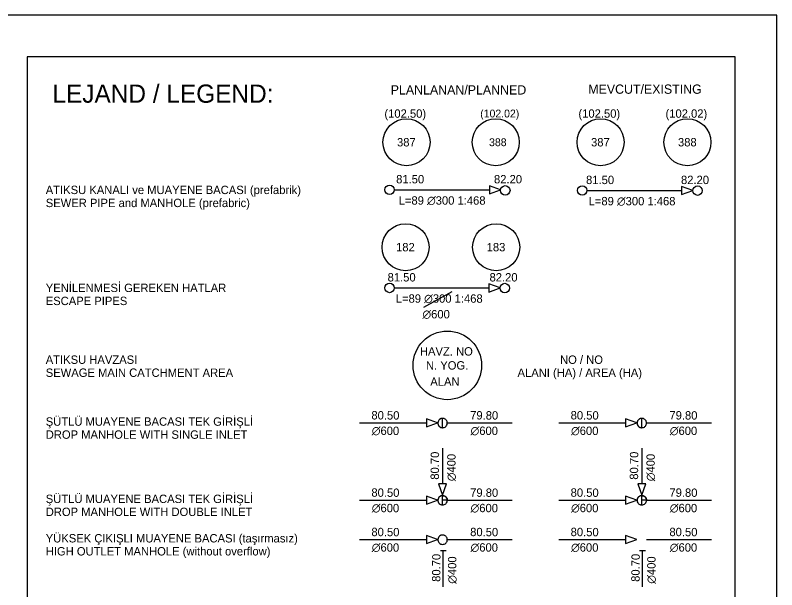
# Model space of a CAD drawing. Extents: x -10 to 1145, y -10 to 821.
# Drawn here: x 962.1 to 1145, y 683 to 821 of the extents above; entities that cross this region are included whole.
import ezdxf

# ---------------------------------------------------------------- set-up
doc = ezdxf.new("R2010")
doc.units = 0
for name, color, linetype in [('Level 1', 7, 'Continuous'), ('Level 10', 7, 'Continuous'), ('Level 11', 7, 'Continuous'), ('Level 12', 7, 'Continuous'), ('Level 13', 7, 'Continuous'), ('Level 15', 7, 'Continuous'), ('Level 16', 7, 'Continuous'), ('Level 17', 7, 'Continuous'), ('Level 31', 7, 'Continuous'), ('Level 32', 7, 'Continuous'), ('Level 39', 7, 'Continuous'), ('Level 51', 7, 'Continuous'), ('Level 52', 7, 'Continuous')]:
    doc.layers.add(name, color=color, linetype=linetype)

msp = doc.modelspace()

# ---------------------------------------------------------------- linework, layer by layer
at = {"layer": 'Level 10'}
for points in [[(1063.61, 723.04), (1063.61, 722.9), (1063.65, 722.68), (1063.73, 722.52), (1063.84, 722.34), (1063.98, 722.17), (1064.11, 722.08), (1064.3, 721.98), (1064.49, 721.92), (1064.74, 721.89), (1064.97, 721.92), (1065.16, 721.97), (1065.36, 722.06), (1065.5, 722.15), (1065.64, 722.3), (1065.71, 722.42), (1065.82, 722.63), (1065.86, 722.82), (1065.88, 722.99), (1065.86, 723.19), (1065.82, 723.38), (1065.76, 723.52), (1065.63, 723.74), (1065.5, 723.86), (1065.33, 723.97), (1065.23, 724.04), (1065.11, 724.09), (1064.92, 724.12), (1064.75, 724.15), (1064.57, 724.12), (1064.36, 724.09), (1064.21, 724.01), (1063.99, 723.86), (1063.86, 723.7), (1063.73, 723.51), (1063.65, 723.27), (1063.61, 723.01)], [(1111.46, 723.04), (1111.46, 722.9), (1111.5, 722.68), (1111.57, 722.52), (1111.68, 722.34), (1111.83, 722.17), (1111.96, 722.08), (1112.14, 721.98), (1112.34, 721.92), (1112.59, 721.89), (1112.82, 721.92), (1113.01, 721.97), (1113.21, 722.06), (1113.35, 722.15), (1113.48, 722.3), (1113.56, 722.42), (1113.67, 722.63), (1113.7, 722.82), (1113.72, 722.99), (1113.7, 723.19), (1113.67, 723.38), (1113.6, 723.52), (1113.47, 723.74), (1113.35, 723.86), (1113.18, 723.97), (1113.08, 724.04), (1112.96, 724.09), (1112.76, 724.12), (1112.6, 724.15), (1112.41, 724.12), (1112.21, 724.09), (1112.06, 724.01), (1111.84, 723.86), (1111.7, 723.7), (1111.57, 723.51), (1111.5, 723.27), (1111.46, 723.01)], [(1063.61, 704.48), (1063.61, 704.34), (1063.65, 704.12), (1063.73, 703.96), (1063.84, 703.78), (1063.98, 703.61), (1064.11, 703.52), (1064.3, 703.42), (1064.49, 703.35), (1064.74, 703.33), (1064.97, 703.35), (1065.16, 703.41), (1065.36, 703.49), (1065.5, 703.59), (1065.64, 703.74), (1065.71, 703.86), (1065.82, 704.06), (1065.86, 704.26), (1065.88, 704.42), (1065.86, 704.63), (1065.82, 704.82), (1065.76, 704.96), (1065.63, 705.18), (1065.5, 705.3), (1065.33, 705.41), (1065.23, 705.48), (1065.11, 705.52), (1064.92, 705.56), (1064.75, 705.59), (1064.57, 705.56), (1064.36, 705.52), (1064.21, 705.45), (1063.99, 705.3), (1063.86, 705.13), (1063.73, 704.95), (1063.65, 704.71), (1063.61, 704.45)], [(1111.46, 704.48), (1111.46, 704.34), (1111.5, 704.12), (1111.57, 703.96), (1111.68, 703.78), (1111.83, 703.61), (1111.96, 703.52), (1112.14, 703.42), (1112.34, 703.35), (1112.59, 703.33), (1112.82, 703.35), (1113.01, 703.41), (1113.21, 703.49), (1113.35, 703.59), (1113.48, 703.74), (1113.56, 703.86), (1113.67, 704.06), (1113.7, 704.26), (1113.72, 704.42), (1113.7, 704.63), (1113.67, 704.82), (1113.6, 704.96), (1113.47, 705.18), (1113.35, 705.3), (1113.18, 705.41), (1113.08, 705.48), (1112.96, 705.52), (1112.76, 705.56), (1112.6, 705.59), (1112.41, 705.56), (1112.21, 705.52), (1112.06, 705.45), (1111.84, 705.3), (1111.7, 705.13), (1111.57, 704.95), (1111.5, 704.71), (1111.46, 704.45)], [(1063.61, 695.01), (1063.61, 694.87), (1063.65, 694.65), (1063.73, 694.49), (1063.84, 694.31), (1063.98, 694.14), (1064.11, 694.05), (1064.3, 693.95), (1064.49, 693.88), (1064.74, 693.86), (1064.97, 693.88), (1065.16, 693.94), (1065.36, 694.02), (1065.5, 694.12), (1065.64, 694.27), (1065.71, 694.39), (1065.82, 694.59), (1065.86, 694.79), (1065.88, 694.95), (1065.86, 695.16), (1065.82, 695.35), (1065.76, 695.49), (1065.63, 695.71), (1065.5, 695.83), (1065.33, 695.94), (1065.23, 696), (1065.11, 696.05), (1064.92, 696.09), (1064.75, 696.12), (1064.57, 696.09), (1064.36, 696.05), (1064.21, 695.98), (1063.99, 695.83), (1063.86, 695.66), (1063.73, 695.48), (1063.65, 695.24), (1063.61, 694.98)]]:
    msp.add_lwpolyline(points, dxfattribs=at)
for points in [[(1064.76, 721.89), (1064.75, 724.15), (1064.49, 724.1), (1064.39, 724.09), (1064.27, 724.04), (1064.17, 723.97), (1064, 723.86), (1063.87, 723.74), (1063.74, 723.52), (1063.68, 723.38), (1063.65, 723.24), (1063.64, 723.19), (1063.63, 723.09), (1063.62, 722.99), (1063.64, 722.82), (1063.68, 722.63), (1063.79, 722.42), (1063.86, 722.3), (1063.97, 722.19), (1064, 722.15), (1064.14, 722.06), (1064.28, 721.99), (1064.33, 721.97), (1064.48, 721.93), (1064.53, 721.92), (1064.64, 721.9)], [(1112.61, 721.89), (1112.6, 724.15), (1112.33, 724.1), (1112.24, 724.09), (1112.12, 724.04), (1112.01, 723.97), (1111.85, 723.86), (1111.72, 723.74), (1111.59, 723.52), (1111.53, 723.38), (1111.5, 723.24), (1111.49, 723.19), (1111.48, 723.09), (1111.47, 722.99), (1111.49, 722.82), (1111.53, 722.63), (1111.64, 722.42), (1111.71, 722.3), (1111.81, 722.19), (1111.85, 722.15), (1111.99, 722.06), (1112.13, 721.99), (1112.18, 721.97), (1112.33, 721.93), (1112.37, 721.92), (1112.49, 721.9)], [(1064.74, 703.33), (1064.75, 705.59), (1064.57, 705.56), (1064.46, 705.54), (1064.36, 705.52), (1064.25, 705.48), (1064.15, 705.41), (1063.98, 705.3), (1063.86, 705.18), (1063.73, 704.96), (1063.66, 704.82), (1063.63, 704.68), (1063.63, 704.63), (1063.62, 704.53), (1063.61, 704.42), (1063.63, 704.26), (1063.66, 704.06), (1063.77, 703.86), (1063.85, 703.74), (1063.95, 703.63), (1063.98, 703.59), (1064.12, 703.49), (1064.27, 703.43), (1064.32, 703.41), (1064.46, 703.37), (1064.51, 703.35), (1064.63, 703.34)], [(1064.74, 704.46), (1064.75, 705.59), (1064.86, 705.57), (1064.97, 705.56), (1065.07, 705.53), (1065.16, 705.51), (1065.26, 705.46), (1065.36, 705.42), (1065.43, 705.37), (1065.5, 705.32), (1065.57, 705.25), (1065.64, 705.17), (1065.67, 705.11), (1065.71, 705.05), (1065.77, 704.95), (1065.82, 704.85), (1065.85, 704.71), (1065.86, 704.62), (1065.87, 704.53), (1065.88, 704.49), (1065.87, 704.49)], [(1112.59, 703.33), (1112.6, 705.59), (1112.41, 705.56), (1112.31, 705.54), (1112.21, 705.52), (1112.1, 705.48), (1112, 705.41), (1111.83, 705.3), (1111.7, 705.18), (1111.57, 704.96), (1111.51, 704.82), (1111.48, 704.68), (1111.47, 704.63), (1111.46, 704.53), (1111.45, 704.42), (1111.47, 704.26), (1111.51, 704.06), (1111.62, 703.86), (1111.69, 703.74), (1111.8, 703.63), (1111.83, 703.59), (1111.97, 703.49), (1112.11, 703.43), (1112.16, 703.41), (1112.31, 703.37), (1112.36, 703.35), (1112.47, 703.34)], [(1112.58, 704.46), (1112.6, 705.59), (1112.7, 705.57), (1112.82, 705.56), (1112.92, 705.53), (1113.01, 705.51), (1113.11, 705.46), (1113.21, 705.42), (1113.28, 705.37), (1113.35, 705.32), (1113.41, 705.25), (1113.48, 705.17), (1113.52, 705.11), (1113.56, 705.05), (1113.61, 704.95), (1113.67, 704.85), (1113.7, 704.71), (1113.71, 704.62), (1113.72, 704.53), (1113.72, 704.49), (1113.72, 704.49)]]:
    msp.add_lwpolyline(points, close=True, dxfattribs=at)
for centre in [(1052, 779.06), (1079.81, 778.92), (1098.29, 778.89), (1125.98, 778.85), (1052, 755.47), (1079.68, 755.46)]:
    msp.add_circle(centre, 1.13, dxfattribs=at)
at = {"layer": 'Level 11'}
for centre in [(1056.08, 790.49), (1077.51, 790.49), (1102.68, 790.49), (1123.55, 790.49), (1055.85, 765.27), (1077.61, 765.27)]:
    msp.add_circle(centre, 5.65, dxfattribs=at)
at = {"layer": 'Level 15'}
for p, q in [((1053.13, 779.03), (1075.98, 779.03)), ((1099.43, 778.87), (1122.15, 778.87)), ((1053.13, 755.47), (1075.85, 755.47)), ((1044.82, 723.05), (1060.86, 723.05)), ((1065.73, 723.05), (1081.47, 723.05)), ((1092.67, 723.05), (1108.7, 723.05)), ((1113.57, 723.05), (1129.32, 723.05)), ((1064.74, 717.01), (1064.74, 708.39)), ((1112.58, 717.01), (1112.58, 708.39)), ((1044.82, 704.49), (1060.86, 704.49)), ((1065.87, 704.49), (1081.47, 704.49)), ((1092.67, 704.49), (1108.7, 704.49)), ((1113.72, 704.49), (1129.32, 704.49)), ((1044.82, 695.02), (1060.86, 695.02)), ((1065.87, 695.02), (1081.47, 695.02)), ((1092.67, 695.02), (1108.7, 695.02)), ((1113.72, 695.02), (1129.32, 695.02)), ((1064.22, 692.36), (1065.63, 692.36)), ((1064.92, 683.69), (1064.92, 692.36)), ((1112.06, 692.36), (1113.48, 692.36)), ((1112.77, 683.69), (1112.77, 692.36))]:
    msp.add_line(p, q, dxfattribs=at)
at = {"layer": 'Level 16'}
for points in [[(1078.68, 779.03), (1075.98, 780), (1075.98, 778.07)], [(1124.85, 778.87), (1122.15, 779.84), (1122.15, 777.9)], [(1078.56, 755.47), (1075.85, 756.43), (1075.85, 754.5)], [(1063.56, 723.05), (1060.86, 724.02), (1060.86, 722.08)], [(1111.41, 723.05), (1108.7, 724.02), (1108.7, 722.08)], [(1064.74, 705.68), (1065.7, 708.39), (1063.77, 708.39)], [(1112.58, 705.68), (1113.55, 708.39), (1111.62, 708.39)], [(1063.56, 704.49), (1060.86, 705.45), (1060.86, 703.52)], [(1111.41, 704.49), (1108.7, 705.45), (1108.7, 703.52)], [(1063.56, 695.02), (1060.86, 695.98), (1060.86, 694.05)], [(1111.41, 695.02), (1108.7, 695.98), (1108.7, 694.05)]]:
    msp.add_lwpolyline(points, close=True, dxfattribs=at)
at = {"layer": 'Level 17'}
msp.add_line((1060.22, 750.87), (1067.07, 754.59), dxfattribs=at)
at = {"layer": 'Level 31'}
msp.add_circle((1065.88, 736.87), 8.24, dxfattribs=at)
at = {"layer": 'Level 51'}
msp.add_lwpolyline([(-10, -10), (1145, -10), (1145, 821), (-10, 821)], close=True, dxfattribs=at)
at = {"layer": 'Level 52'}
msp.add_lwpolyline([(965, 287), (1135, 287), (1135, 811), (965, 811)], close=True, dxfattribs=at)

# ---------------------------------------------------------------- texts
at = {"layer": 'Level 1'}
for s, height, p in [('LEJAND / LEGEND:', 4.3826, (971.05, 799.97)), ('PLANLANAN/PLANNED', 2.2228, (1052.29, 801.95)), ('MEVCUT/EXISTING', 2.2228, (1099.73, 802.13)), ('ATIKSU KANALI ve MUAYENE BACASI (prefabrik)', 2.0119, (969.44, 778.03)), ('SEWER PIPE and MANHOLE (prefabric)', 2.0119, (969.44, 774.9)), ('YENİLENMESİ GEREKEN HATLAR', 2.0119, (969.44, 754.49)), ('ESCAPE PIPES', 2.0119, (969.44, 751.36)), ('ATIKSU HAVZASI', 2.0119, (969.44, 737.24)), ('SEWAGE MAIN CATCHMENT AREA', 2.0119, (969.44, 734.11)), ('ŞÜTLÜ MUAYENE BACASI TEK GİRİŞLİ', 2.0119, (969.44, 722.37)), ('DROP MANHOLE WITH SINGLE INLET', 2.0119, (969.44, 719.24)), ('ŞÜTLÜ MUAYENE BACASI TEK GİRİŞLİ', 2.0119, (969.44, 703.8)), ('DROP MANHOLE WITH DOUBLE INLET', 2.0119, (969.44, 700.68)), ('YÜKSEK ÇIKIŞLI MUAYENE BACASI (taşırmasız)', 2.0119, (969.44, 694.33)), ('HIGH OUTLET MANHOLE (without overflow)', 2.0119, (969.44, 691.2))]:
    msp.add_text(s, height=height, rotation=360, dxfattribs=at).set_placement(p)
at = {"layer": 'Level 12'}
for s, height, p in [('387', 2.012, (1053.8, 789.48)), ('388', 1.883, (1075.91, 789.54)), ('387', 2.012, (1100.4, 789.48)), ('388', 2.012, (1121.27, 789.48)), ('182', 2.012, (1053.57, 764.27)), ('183', 2.012, (1075.33, 764.27))]:
    msp.add_text(s, height=height, rotation=360, dxfattribs=at).set_placement(p)
at = {"layer": 'Level 13'}
for s, height, p in [('(102.50)', 2.012, (1050.77, 796.37)), ('(102.02)', 1.883, (1073.78, 796.44)), ('(102.50)', 2.012, (1097.37, 796.37)), ('(102.02)', 2.012, (1118.28, 796.37))]:
    msp.add_text(s, height=height, rotation=360, dxfattribs=at).set_placement(p)
at = {"layer": 'Level 17'}
for s, height, rotation, p in [('81.50', 2.012, 360, (1053.59, 780.6)), ('82.20', 2.012, 360, (1077.09, 780.6)), ('81.50', 2.012, 360, (1099.2, 780.43)), ('82.20', 2.012, 360, (1122, 780.43)), ('L=89 ∅300 1:468', 2.0119, 359.987, (1054.2, 775.49)), ('L=89 ∅300 1:468', 2.0119, 359.987, (1099.81, 775.33)), ('81.50', 2.012, 360, (1051.54, 757.03)), ('82.20', 2.012, 360, (1076.02, 757.03)), ('L=89 ∅300 1:468', 2.0119, 359.987, (1053.51, 751.93)), (' ∅600 ', 2.012, 359.987, (1059.16, 748.16)), ('80.50', 2.012, 359.5872, (1047.64, 723.89)), ('79.80', 2.012, 359.5872, (1071.36, 723.89)), ('80.50', 2.012, 359.5872, (1095.49, 723.89)), ('79.80', 2.012, 359.5872, (1119.21, 723.89)), ('∅600', 2.012, 359.5872, (1047.74, 720.18)), ('∅600', 2.012, 359.5872, (1071.46, 720.18)), ('∅600', 2.012, 359.5872, (1095.59, 720.18)), ('∅600', 2.012, 359.5872, (1119.31, 720.18)), ('80.70', 2.012, 89.5872, (1063.86, 709.4)), ('∅400', 2.012, 89.5872, (1067.83, 709.04)), ('80.70', 2.012, 89.5872, (1111.7, 709.4)), ('∅400', 2.012, 89.5872, (1115.67, 709.04)), ('80.50', 2.012, 359.5872, (1047.64, 705.32)), ('79.80', 2.012, 359.5872, (1071.36, 705.32)), ('80.50', 2.012, 359.5872, (1095.49, 705.32)), ('79.80', 2.012, 359.5872, (1119.21, 705.32)), ('∅600', 2.012, 359.5872, (1047.74, 701.62)), ('∅600', 2.012, 359.5872, (1071.46, 701.62)), ('∅600', 2.012, 359.5872, (1095.59, 701.62)), ('∅600', 2.012, 359.5872, (1119.31, 701.62)), ('80.50', 2.012, 359.5872, (1047.64, 695.85)), ('80.50', 2.012, 359.5872, (1071.36, 695.85)), ('80.50', 2.012, 359.5872, (1095.49, 695.85)), ('80.50', 2.012, 359.5872, (1119.21, 695.85)), ('∅600', 2.012, 359.5872, (1047.74, 692.15)), ('∅600', 2.012, 359.5872, (1071.46, 692.15)), ('∅600', 2.012, 359.5872, (1095.59, 692.15)), ('∅600', 2.012, 359.5872, (1119.31, 692.15)), ('80.70', 2.012, 89.5872, (1064.21, 684.86)), ('80.70', 2.012, 89.5872, (1112.06, 684.86)), ('∅400', 2.012, 89.5872, (1068.01, 684.4)), ('∅400', 2.012, 89.5872, (1115.86, 684.4))]:
    msp.add_text(s, height=height, rotation=rotation, dxfattribs=at).set_placement(p)
at = {"layer": 'Level 32'}
for s, p in [('HAVZ. NO', (1059.3, 739.23)), ('N. YOG.', (1060.75, 735.86)), ('ALAN', (1061.79, 731.97))]:
    msp.add_text(s, height=2.012, rotation=360, dxfattribs=at).set_placement(p)
at = {"layer": 'Level 39'}
for s, height, p in [('NO / NO', 2.012, (1092.95, 737.24)), ('ALANI (HA) / AREA (HA)', 2.0119, (1082.74, 734.11))]:
    msp.add_text(s, height=height, rotation=360, dxfattribs=at).set_placement(p)

doc.saveas('drawing.dxf')
